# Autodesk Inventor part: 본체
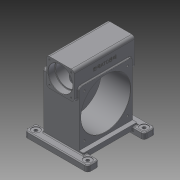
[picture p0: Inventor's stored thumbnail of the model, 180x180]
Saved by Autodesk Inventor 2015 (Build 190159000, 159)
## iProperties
Created: 2025-06
Part Number: 본체
Material: 일반
Document SubType Name: Modeling
Designer: User
Density: 1 g/cm^3
Appearance: 기본값
Author: User
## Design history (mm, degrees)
sketch "스케치2"
  geometry: L1 (93, -103)-(-93, -103); L2 (-93, -103)-(-93, 103); L3 (-93, 103)-(93, 103); L4 (93, 103)-(93, -103); L5 (93, -103)-(-93, 103); L6 (-93, -103)-(93, 103); 1 further point
  constraints: 12 end point, 2 midpoint, 2 parallel, 1 horizontal, 1 perpendicular
  dimensions: "d0" = 186 distance of L2.end L3.end; "d1" = 206 distance of L1.end L2.end
extrude "돌출1" new body sketch "스케치2" distance "d2" = 55; taper "d3" = 0 deg; dims "d48" = 70, "d49" = 0
sketch "스케치4"
  geometry: L1 (46, 158)-(-50, 158); L2 (-50, 158)-(-50, 62); L3 (-50, 62)-(46, 62); L4 (46, 62)-(46, 158); L5 (46, 158)-(-50, 62); L6 (-50, 158)-(46, 62); L7 (70, 103)-(70, -103) reference; L8 (70, -103)-(-55, -103) reference; L9 (-55, -103)-(-55, 103) reference; L10 (-55, 103)-(70, 103) reference; 2 further points
  constraints: 12 end point, 2 midpoint, 2 parallel, 1 horizontal, 1 perpendicular
  dimensions: "d6" = 96 distance of L3.end L2.end; "d7" = 96 distance of L2.end L1.end; "d9" = 5 distance between parallel lines of L9 L2; "d72" = 261 distance between parallel lines of L8 L1
extrude "돌출2" join sketch "스케치4" stored distance "d10" = 210; taper "d11" = 0 deg
sketch "스케치9"
  geometry: L1 (50, 158)-(-46, 158) reference; L2 (50, 62)-(50, 158) reference; C1 r 42.5 at (2, 110); 3 further points
  constraints: 2 midpoint, 1 centre point, 1 horizontal alignment, 1 vertical alignment
  dimensions: "d21" = 85 diameter of C1
extrude "돌출6" cut sketch "스케치9" distance "d22" = 23; taper "d23" = 0 deg
sketch "스케치10"
  geometry: C1 r 42.5 at (0, 0) reference; C2 r 38.5 at (0, 0); 1 further point
  constraints: 1 centre point, 1 coincident
  dimensions: "d24" = 77 diameter of C2
extrude "돌출7" cut sketch "스케치10" stored distance "d25" = 0; taper "d26" = 0 deg
sketch "스케치11"
  geometry: C1 r 38.5 at (2, -110) reference; C2 r 42.5 at (2, -110); 1 further point
  constraints: 1 centre point, 1 coincident
  dimensions: "d27" = 85 diameter of C2
extrude "돌출8" cut sketch "스케치11" distance "d28" = 23; taper "d29" = 0 deg
node "작업 평면3"
sketch "스케치16"
  geometry: L1 (165, -211)-(-55, -211); L2 (-55, -211)-(-55, -171); L3 (-55, -171)-(165, -171); L4 (165, -171)-(165, -211); 2 further points
  constraints: 8 end point, 2 parallel, 1 horizontal, 1 midpoint, 1 perpendicular, 1 vertical alignment
  dimensions: "d58" = 40 distance between parallel lines of L3 L1; "d59" = 220 distance between parallel lines of L4 L2; "d60" = 118 distance of point (55, -93) point (55, -211)
extrude "돌출11" join sketch "스케치16" distance "d61" = 20; taper "d62" = 0 deg
sketch "스케치20"
  geometry: L1 (0, -171)-(55, -171) reference; L2 (55, -171)-(55, -211) reference; L3 (55, -211)-(-165, -211) reference; L4 (-165, -211)-(-165, -171) reference; L5 (-165, -171)-(-125, -171) reference; L6 (-125, -186)-(-125, -171) reference; L7 (0, -186)-(-125, -186) reference; L8 (0, -171)-(0, -186) reference; L9 (0, 0)-(0, -171) reference; L10 (-125, 0)-(0, 0) reference; L11 (-125, -171)-(-125, 0) reference; 2 further points
  dimensions: "d63" = 98 vertical distance of point (-55, -93) point (35, -191); "d64" = 90 horizontal distance of point (-55, -93) point (35, -191)
hole "구멍2" sketch "스케치20" at (35, -191) diameter "d65" = 11; stored, may be unused: countersink angle "d69" = 90 deg, drill point angle "d71" = 118 deg; dims "d66" = 6, "d67" = 28, "d68" = 2, "d70" = 8
sketch "스케치25"
  geometry: L1 (0, 0)-(0, 156) reference; L2 (0, -15)-(-15, -15); L3 (-15, -15)-(-15, 171); L4 (-15, 171)-(0, 171); L5 (0, 171)-(0, -15); 3 further points
  constraints: 8 end point, 2 midpoint, 2 parallel, 1 coincident, 1 horizontal, 1 horizontal alignment, 1 perpendicular
  dimensions: "d74" = 15 distance of L3.end L4.end; "d75" = 186 distance between parallel lines of L2 L4
extrude "돌출12" join sketch "스케치25" distance "d76" = 17; taper "d77" = 0 deg
sketch "스케치26"
  geometry: L1 (113, -118)-(113, -78) reference; C1 r 86 at (-10, 0); 1 further point
  constraints: 1 centre point, 1 horizontal alignment
  dimensions: "d78" = 123 distance from line of L1 C1.centre; "d79" = 172 diameter of C1
extrude "돌출13" cut sketch "스케치26" distance "d80" = 102; taper "d81" = 0 deg
sketch "스케치28"
  geometry: C1 r 86 at (0, 0) reference; C2 r 31 at (0, 0); 1 further point
  constraints: 1 centre point, 1 coincident
  dimensions: "d82" = 62 diameter of C2
extrude "돌출14" cut sketch "스케치28" distance "d83" = 16; taper "d84" = 0 deg
sketch "스케치29"
  geometry: C1 r 31 at (0, 0) reference; C2 r 27 at (0, 0); 1 further point
  constraints: 1 centre point, 1 coincident
  dimensions: "d85" = 54 diameter of C2
extrude "돌출15" cut sketch "스케치29" distance "d86" = 3; taper "d87" = 0 deg
fillet "모깎기3" dims "d90" = 10
fillet "모깎기4" dims "d91" = 10
fillet "모깎기5" dims "d92" = 3
sketch "스케치30"
  geometry: A1 r 10 centre (-36, 72) between (-46, 72) and (-36, 62) reference; A2 r 10 centre (40, 72) between (40, 62) and (50, 72) reference; A3 r 10 centre (40, 148) between (50, 148) and (40, 158) reference; A4 r 10 centre (-36, 148) between (-36, 158) and (-46, 148) reference; 1 further point
hole "구멍3" sketch "스케치30" at (-36, 148), (40, 148), (40, 72), (-36, 72) diameter "d93" = 4.917; stored, may be unused: countersink angle "d97" = 90 deg, drill point angle "d99" = 118 deg; dims "d94" = 12, "d95" = 28, "d96" = 2, "d98" = 14
sketch "스케치32"
  geometry: L1 (65, 75)-(-85, 75); L2 (-85, 75)-(-85, -75); L3 (-85, -75)-(65, -75); L4 (65, -75)-(65, 75); L5 (65, 75)-(-85, -75); L6 (-85, 75)-(65, -75); C1 r 86 at (-10, 0) reference; 2 further points
  constraints: 12 end point, 3 midpoint, 2 parallel, 1 coincident, 1 horizontal, 1 perpendicular
  dimensions: "d113" = 150 distance of L3.end L2.end; "d114" = 150 distance of L2.end L1.end
hole "구멍5" sketch "스케치32" at (-85, -75), (-85, 75), (65, 75), (65, -75) diameter "d115" = 6.647; stored, may be unused: countersink angle "d119" = 90 deg, drill point angle "d121" = 118 deg; dims "d116" = 16, "d117" = 28, "d118" = 2, "d120" = 18
fillet "모깎기6" dims "d122" = 10
fillet "모깎기7" dims "d123" = 3
fillet "모깎기8" dims "d124" = 3
fillet "모깎기9" dims "d125" = 3
fillet "모깎기10" dims "d126" = 3
sketch "스케치33"
  geometry: L1 (-10, 210)-(-10, 0) reference; 2 further points
  constraints: 1 other
  dimensions: "d127" = 30 distance from line of L1 point (20, 106.005)
feature "엠보싱1" sketch "스케치33" dims "d128" = 0.5, "d129" = 0
fillet "모깎기11" dims "d130" = 1
chamfer "모따기1" distance "d131" = 1; stored, may be unused: second distance "d132" = 2, angle "d133" = 45 deg
fillet "모깎기12" dims "d134" = 3
fillet "모깎기13" dims "d135" = 3
chamfer "모따기2" distance "d136" = 1; stored, may be unused: second distance "d137" = 2, angle "d138" = 45 deg
fillet "모깎기14" dims "d139" = 1.1
node "솔리드1"
mirror "대칭3"
mirror "대칭4"
mirror "대칭5"
node "절단 모서리 투영1"
node "절단 모서리 투영4"
